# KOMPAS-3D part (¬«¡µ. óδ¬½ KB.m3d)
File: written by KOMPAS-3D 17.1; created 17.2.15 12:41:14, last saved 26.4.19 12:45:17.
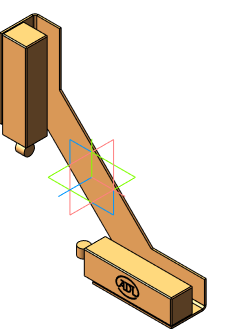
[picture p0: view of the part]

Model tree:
1. Операция без истории:2  (labels: Сталь 20  ГОСТ 1050-88)

Referenced files in \\adlc.lan\data\АДЛ_ПКД\3D-модели\ADL production\Дисковые поворотные затворы ГРАНВЭЛ\межфланцевый с рукояткой MN и конц. выкл\KOMPAS 3D\: Гранвэл Ду100 Ру1,6 с концевиками.a3d
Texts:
  Толщина листового тела
  Глубина освобождения сгиба
  Ширина освобождения сгиба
